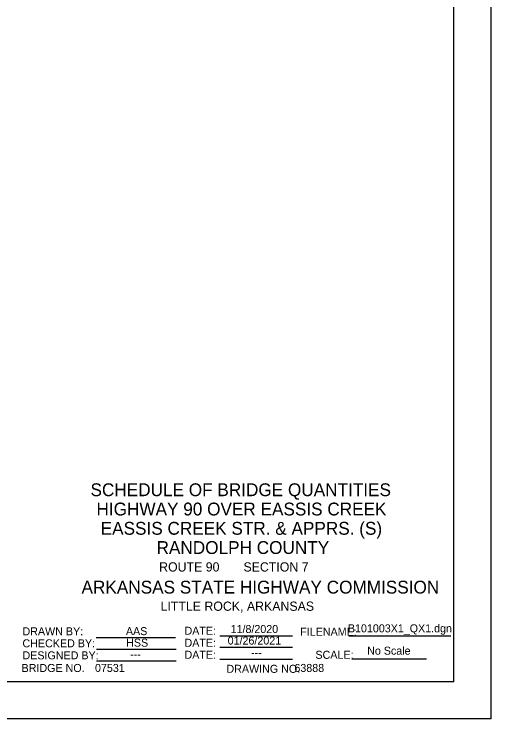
# Model space of a CAD drawing. Extents: x 188 to 14744886, y 129 to 1829278.
# Drawn here: x 214.44 to 221.88, y 128.51 to 139.51 of the extents above; entities that cross this region are included whole.
import ezdxf

# ---------------------------------------------------------------- set-up
doc = ezdxf.new("R2010")
doc.units = 0
for name, color, linetype in [('B_Copy In', 7, 'Continuous'), ('B_Text', 7, 'Continuous'), ('B_Title Text', 7, 'Continuous'), ('R_Border', 7, 'Continuous')]:
    doc.layers.add(name, color=color, linetype=linetype)

msp = doc.modelspace()

# ---------------------------------------------------------------- linework, layer by layer
at = {"layer": 'B_Text'}
for p, q in [((217.652, 129.812), (218.786, 129.812)), ((219.664, 129.812), (221.26, 129.812)), ((215.719, 129.782), (216.962, 129.782)), ((215.726, 129.602), (216.97, 129.602)), ((217.652, 129.632), (218.786, 129.632)), ((217.652, 129.632), (218.786, 129.632)), ((215.726, 129.422), (216.97, 129.422)), ((217.652, 129.444), (218.786, 129.444)), ((219.71, 129.452), (220.876, 129.452))]:
    msp.add_line(p, q, dxfattribs=at)
at = {"layer": 'R_Border'}
for q in [(221.306, 149.937), (189.399, 129.091)]:
    msp.add_line((221.306, 129.091), q, dxfattribs=at)
msp.add_lwpolyline([(187.883, 150.514), (221.883, 150.514), (221.883, 128.514), (187.883, 128.514)], close=True, dxfattribs=at)

# ---------------------------------------------------------------- texts
at = {"layer": 'B_Copy In'}
for s, height, p in [('SCHEDULE OF BRIDGE QUANTITIES', 0.2004, (215.633, 131.99)), ('HIGHWAY 90 OVER EASSIS CREEK', 0.2004, (215.726, 131.689)), ('EASSIS CREEK STR. & APPRS. (S)', 0.2004, (215.792, 131.388)), ('RANDOLPH COUNTY', 0.2004, (216.664, 131.088)), ('AAS', 0.1248, (216.186, 129.821)), ('11/8/2020', 0.1248, (217.82, 129.854)), ('B101003X1_QX1.dgn', 0.1248, (219.651, 129.865)), ('01/26/2021', 0.1248, (217.774, 129.674)), ('HSS', 0.1248, (216.19, 129.641)), ('No Scale', 0.1248, (219.952, 129.516)), ('---', 0.1248, (216.252, 129.461)), ('---', 0.1248, (218.139, 129.487)), ('07531', 0.1248, (215.703, 129.247)), ('63888', 0.1248, (218.816, 129.247))]:
    msp.add_text(s, height=height, dxfattribs=at).set_placement(p)
at = {"layer": 'B_Text'}
for s, p in [('DRAWN BY:', (214.571, 129.818)), ('DATE:', (217.1, 129.827)), ('FILENAME:', (218.907, 129.812)), ('CHECKED BY:', (214.571, 129.631)), ('DATE:', (217.1, 129.639)), ('DESIGNED BY:', (214.571, 129.443)), ('DATE:', (217.1, 129.452)), ('SCALE:', (219.144, 129.452)), ('BRIDGE NO.', (214.557, 129.246)), ('DRAWING NO.', (217.755, 129.233))]:
    msp.add_text(s, height=0.125, dxfattribs=at).set_placement(p)
at = {"layer": 'B_Title Text'}
msp.add_text('     ROUTE 90       SECTION 7', height=0.144, rotation=360, dxfattribs=at).set_placement((216.437, 130.814))
for s, height, p in [('ARKANSAS STATE HIGHWAY COMMISSION', 0.2004, (215.493, 130.47)), ('LITTLE ROCK, ARKANSAS', 0.144, (216.726, 130.201))]:
    msp.add_text(s, height=height, dxfattribs=at).set_placement(p)

doc.saveas('drawing.dxf')
